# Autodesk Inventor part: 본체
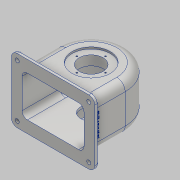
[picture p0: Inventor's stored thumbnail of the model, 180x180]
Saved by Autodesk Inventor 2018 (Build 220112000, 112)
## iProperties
Created: 2022-09
Part Number: 본체
Material: 알루미늄 6061
Document SubType Name: Modeling
Designer: home
Density: 2.7 g/cm^3
Appearance: 알루미늄 - 평지
Author: home
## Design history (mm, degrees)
sketch "스케치1"
  geometry: L1 (-57, 0)-(57, 0); L2 (57, 0)-(57, -64); L3 (57, -64)-(-57, -64); L4 (-57, -64)-(-57, 0); A1 r 57 centre (0, 0) between (57, 0) and (-57, 0); 1 further point
  constraints: 8 end point, 2 parallel, 2 point on circle, 1 centre point, 1 coincident, 1 horizontal, 1 perpendicular
  dimensions: "d0" = 114 diameter of A1; "d1" = 64 distance of L1.end L2.end
extrude "돌출1" new body sketch "스케치1" stored distance "d2" = 78; taper "d3" = 0 deg
feature "쉘1" dims "d4" = 5
sketch "스케치2"
  geometry: L1 (-57, 0)-(-57, -64) reference; L2 (-57, -64)-(57, -64) reference; L3 (57, -64)-(57, 0) reference; C1 r 31 at (0, 0); A1 r 57 centre (0, 0) between (57, 0) and (-57, 0) reference; 1 further point
  constraints: 1 centre point, 1 coincident
  dimensions: "d5" = 62 diameter of C1
extrude "돌출2" join sketch "스케치2" distance "d6" = 15; taper "d7" = 0 deg
hole "구멍1" diameter "d10" = 35; stored, may be unused: countersink angle "d14" = 90 deg, drill point angle "d16" = 118 deg; dims "d8" = 10, "d9" = 10, "d11" = 6, "d12" = 40, "d13" = 16, "d15" = 30
sketch "스케치3"
  geometry: A1 r 24 centre (0, 0) between (0, 24) and (-24, 0); 3 further points
  constraints: 4 point on circle, 1 centre point, 1 coincident
  dimensions: "d17" = 48 diameter of A1
hole "구멍2" sketch "스케치3" at (0, 24), (-24, 0), (0, -24), (24, 0) diameter "d18" = 2.459; stored, may be unused: countersink angle "d22" = 90 deg, drill point angle "d24" = 118 deg; dims "d19" = 7, "d20" = 40, "d21" = 16, "d23" = 9
node "작업 평면1"
sketch "스케치4"
  geometry: C1 r 28 at (0, 0); 1 further point
  constraints: 1 centre point, 1 coincident
  dimensions: "d26" = 56 diameter of C1
extrude "돌출3" join sketch "스케치4" distance "d27" = 19; taper "d28" = 30 deg
sketch "스케치5"
  geometry: C1 r 32 at (0, 0); 1 further point
  constraints: 1 centre point, 1 coincident
  dimensions: "d29" = 64 diameter of C1
extrude "돌출4" cut sketch "스케치5" distance "d30" = 3; taper "d31" = 0 deg
hole "구멍3" diameter "d34" = 40; stored, may be unused: countersink angle "d38" = 90 deg, drill point angle "d40" = 118 deg; dims "d32" = 10, "d33" = 10, "d35" = 7, "d36" = 40, "d37" = 16, "d39" = 30
sketch "스케치6"
  geometry: L1 (-3, 15)-(117, 15); L2 (127, 5)-(127, -83); L3 (117, -93)-(-3, -93); L4 (-13, -83)-(-13, 5); L5 (-13, 15)-(127, -93); L6 (127, 15)-(-13, -93); L7 (5, -73)-(5, -5) reference; L8 (5, -5)-(109, -5) reference; L9 (109, -5)-(109, -73) reference; L10 (109, -73)-(5, -73) reference; L11 (114, -78)-(114, 0) reference; L12 (0, 0)-(114, 0) reference; L13 (0, -78)-(0, 0) reference; L14 (114, -78)-(0, -78) reference; C1 r 3.3 at (117, 5); C2 r 3.3 at (117, -83); C3 r 3.3 at (-3, 5); C4 r 3.3 at (-3, -83); A1 r 10 centre (117, 5) between (127, 5) and (117, 15); A2 r 10 centre (117, -83) between (117, -93) and (127, -83); A3 r 10 centre (-3, -83) between (-13, -83) and (-3, -93); A4 r 10 centre (-3, 5) between (-3, 15) and (-13, 5); 1 further point
  constraints: 12 end point, 8 centre point, 8 point on circle, 8 point on line, 8 tangent, 4 coincident, 3 equal radius, 2 midpoint, 2 parallel, 1 horizontal, 1 perpendicular
  dimensions: "d41" = 140 distance of L5.end L6.end; "d42" = 108 distance of L6.start L5.end; "d43" = 10 radius of A1; "d44" = 6.6 diameter of C1; "d45" = 6.6 diameter of C2; "d46" = 6.6 diameter of C3; "d47" = 6.6 diameter of C4
extrude "돌출5" join sketch "스케치6" distance "d48" = 7; taper "d49" = 0 deg
fillet "모깎기1" dims "d50" = 14
fillet "모깎기2" dims "d51" = 3
sketch "스케치7"
  geometry: C1 r 1.23 at (24, 0) reference; A1 r 24 centre (0, 0) between (0, 24) and (-24, 0); 3 further points
  constraints: 3 point on circle, 2 coincident, 1 centre point
  dimensions: "d52" = 48 diameter of A1
hole "구멍4" sketch "스케치7" at (0, 24), (-24, 0), (0, -24), (24, 0) diameter "d53" = 2.459; stored, may be unused: countersink angle "d57" = 90 deg, drill point angle "d59" = 118 deg; dims "d54" = 7, "d55" = 40, "d56" = 16, "d58" = 9
node "작업 평면3"
  node "작업 평면2"
sketch "스케치8"
  geometry: C1 r 6 at (0, 0); 1 further point
  constraints: 1 centre point, 1 coincident
  dimensions: "d61" = 12 diameter of C1
extrude "돌출6" join sketch "스케치8" stored distance "d62" = 7; taper "d63" = 0 deg
hole "구멍5" diameter "d66" = 5.188; stored, may be unused: countersink angle "d70" = 90 deg, drill point angle "d72" = 118 deg; dims "d64" = 10, "d65" = 10, "d67" = 20, "d68" = 40, "d69" = 16, "d71" = 20
fillet "모깎기3" dims "d73" = 1
fillet "모깎기4" dims "d74" = 9
sketch "스케치9"
  geometry: L1 (69, -64)-(-19, -64) reference; L2 (25, -64)-(25, -47); L3 (25, -47)-(-14, -47); 1 further point
  constraints: 4 end point, 1 coincident, 1 horizontal, 1 midpoint, 1 vertical, 1 other
  dimensions: "d75" = 17 distance of L2.start L2.end; "d79" = 39 distance of L3.start L3.end
feature "엠보싱1" sketch "스케치9" dims "d0" = 114, "d1" = 64, "d76" = 0.5, "d77" = 0
fillet "모깎기5" dims "d78" = 0.6
node "솔리드1"
node "투영된 루프1"
node "투영된 루프2"
other parameters: "d25" = -19, "d60" = 3
